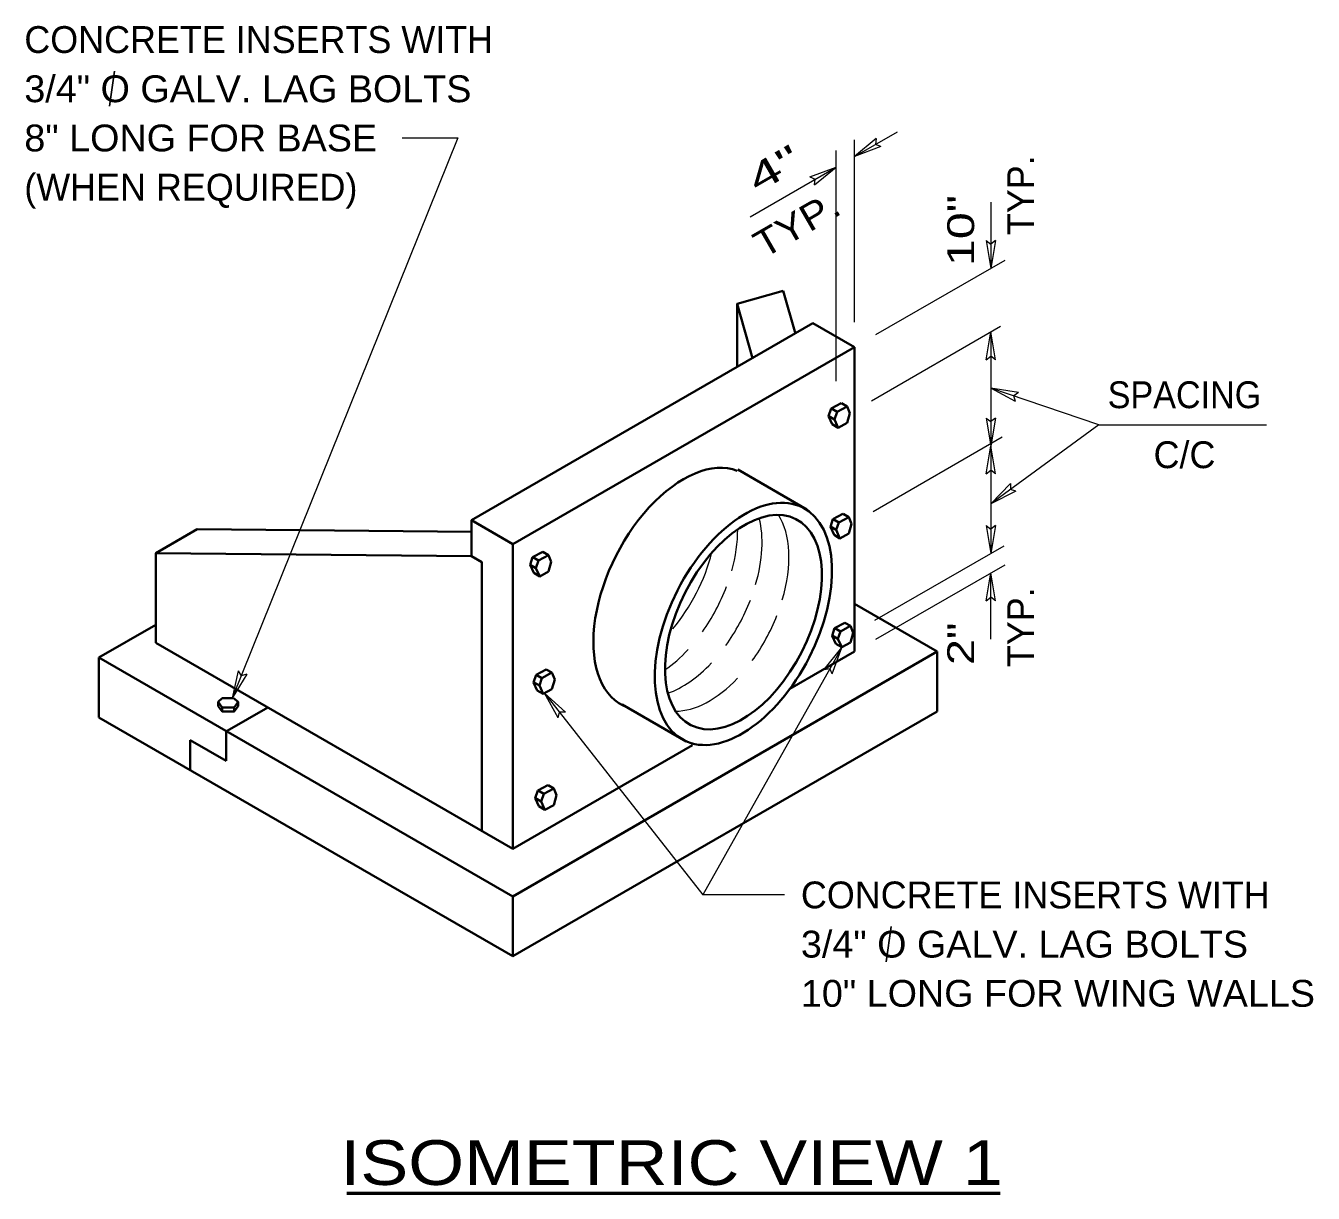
# Model space of a CAD drawing. Extents: x 178962.5 to 178977.5, y 178951.2 to 178972.9.
# Drawn here: x 178962.79 to 178969.26, y 178967.06 to 178972.93 of the extents above; entities that cross this region are included whole.
import ezdxf
from ezdxf.enums import TextEntityAlignment as Align

# ---------------------------------------------------------------- set-up
doc = ezdxf.new("R2010")
doc.units = 0
doc.header["$LTSCALE"] = 0.054
for name, color, linetype, lineweight in [('1', 7, 'Continuous', 35), ('10', 7, 'Continuous', 13), ('12', 7, 'Continuous', 53), ('6', 7, 'Continuous', 13)]:
    doc.layers.add(name, color=color, linetype=linetype, lineweight=lineweight)

msp = doc.modelspace()

# ---------------------------------------------------------------- linework, layer by layer
at = {"layer": '1'}
for p, q in [((178966.65783, 178971.38425), (178966.596, 178971.6)), ((178966.365, 178971.53367), (178966.365, 178971.21692)), ((178965.02958, 178970.44583), (178966.74642, 178971.43708)), ((178966.95458, 178971.31692), (178966.74642, 178971.43708)), ((178965.23767, 178970.32575), (178966.95458, 178971.31692)), ((178966.95458, 178969.78508), (178966.95458, 178971.31692)), ((178966.838, 178971.0075), (178966.82525, 178970.9695)), ((178966.838, 178971.0075), (178966.88842, 178971.0345)), ((178966.83892, 178971.008), (178966.86742, 178970.9915)), ((178966.86742, 178970.9915), (178966.85467, 178970.9535)), ((178966.86742, 178970.9915), (178966.91783, 178971.0185)), ((178966.88925, 178971.035), (178966.91783, 178971.0185)), ((178966.91783, 178971.0185), (178966.93167, 178970.98442)), ((178966.91783, 178970.93525), (178966.93167, 178970.98442)), ((178966.84358, 178970.92883), (178966.82525, 178970.9695)), ((178966.8255, 178970.97025), (178966.85467, 178970.9535)), ((178966.84358, 178970.92883), (178966.87358, 178970.9115)), ((178966.87358, 178970.9115), (178966.85467, 178970.9535)), ((178966.87358, 178970.9115), (178966.91783, 178970.93525)), ((178966.36925, 178970.70042), (178966.71592, 178970.50033)), ((178966.84675, 178970.451), (178966.89717, 178970.478)), ((178966.898, 178970.4785), (178966.92658, 178970.462)), ((178965.03075, 178970.38767), (178963.65083, 178970.40083)), ((178966.84675, 178970.451), (178966.834, 178970.413)), ((178966.85233, 178970.37233), (178966.834, 178970.413)), ((178966.83425, 178970.41375), (178966.86342, 178970.397)), ((178966.84767, 178970.4515), (178966.87617, 178970.435)), ((178966.87617, 178970.435), (178966.86342, 178970.397)), ((178966.87617, 178970.435), (178966.92658, 178970.462)), ((178966.92658, 178970.462), (178966.94042, 178970.42792)), ((178966.92658, 178970.37875), (178966.94042, 178970.42792)), ((178966.85233, 178970.37233), (178966.88233, 178970.355)), ((178966.88233, 178970.355), (178966.86342, 178970.397)), ((178966.88233, 178970.355), (178966.92658, 178970.37875)), ((178963.44275, 178969.83008), (178963.44275, 178970.28058)), ((178965.337, 178970.25975), (178965.38742, 178970.28675)), ((178965.36642, 178970.24375), (178965.41683, 178970.27075)), ((178965.38825, 178970.28725), (178965.41683, 178970.27075)), ((178965.41683, 178970.27075), (178965.43067, 178970.23667)), ((178965.337, 178970.25975), (178965.32425, 178970.22175)), ((178965.34258, 178970.18108), (178965.32425, 178970.22175)), ((178965.3245, 178970.2225), (178965.35367, 178970.20575)), ((178965.33792, 178970.26025), (178965.36642, 178970.24375)), ((178965.36642, 178970.24375), (178965.35367, 178970.20575)), ((178965.37258, 178970.16375), (178965.35367, 178970.20575)), ((178965.41683, 178970.1875), (178965.43067, 178970.23667)), ((178965.34258, 178970.18108), (178965.37258, 178970.16375)), ((178965.37258, 178970.16375), (178965.41683, 178970.1875)), ((178967.37075, 178969.78508), (178966.95458, 178970.02533)), ((178963.15667, 178969.755), (178963.44275, 178969.92017)), ((178966.8555, 178969.90325), (178966.84275, 178969.86525)), ((178966.8555, 178969.90325), (178966.90592, 178969.93025)), ((178966.85642, 178969.90375), (178966.88492, 178969.88725)), ((178966.88492, 178969.88725), (178966.87217, 178969.84925)), ((178966.88492, 178969.88725), (178966.93533, 178969.91425)), ((178966.90675, 178969.93075), (178966.93533, 178969.91425)), ((178966.93533, 178969.91425), (178966.94917, 178969.88017)), ((178963.44275, 178969.83008), (178965.23767, 178968.79375)), ((178966.86108, 178969.82458), (178966.84275, 178969.86525)), ((178966.843, 178969.866), (178966.87217, 178969.84925)), ((178966.86108, 178969.82458), (178966.89108, 178969.80725)), ((178966.89108, 178969.80725), (178966.87217, 178969.84925)), ((178966.89108, 178969.80725), (178966.93533, 178969.831)), ((178966.93533, 178969.831), (178966.94917, 178969.88017)), ((178965.23767, 178968.55342), (178963.15667, 178969.755)), ((178963.15667, 178969.45458), (178963.15667, 178969.755)), ((178966.95458, 178969.78508), (178966.63025, 178969.59767)), ((178967.37075, 178969.48467), (178967.37075, 178969.78508)), ((178965.3545, 178969.6685), (178965.40492, 178969.6955)), ((178965.40575, 178969.696), (178965.43433, 178969.6795)), ((178965.3545, 178969.6685), (178965.34175, 178969.6305)), ((178965.36008, 178969.58983), (178965.34175, 178969.6305)), ((178965.342, 178969.63125), (178965.37117, 178969.6145)), ((178965.35542, 178969.669), (178965.38392, 178969.6525)), ((178965.38392, 178969.6525), (178965.37117, 178969.6145)), ((178965.38392, 178969.6525), (178965.43433, 178969.6795)), ((178965.43433, 178969.6795), (178965.44817, 178969.64542)), ((178965.43433, 178969.59625), (178965.44817, 178969.64542)), ((178965.36008, 178969.58983), (178965.39008, 178969.5725)), ((178965.39008, 178969.5725), (178965.37117, 178969.6145)), ((178965.39008, 178969.5725), (178965.43433, 178969.59625)), ((178963.75633, 178969.53267), (178963.77675, 178969.5505)), ((178963.75633, 178969.53267), (178963.77617, 178969.50467)), ((178963.77617, 178969.50467), (178963.83583, 178969.50467)), ((178963.77617, 178969.50467), (178963.77617, 178969.48325)), ((178963.83317, 178969.5505), (178963.77675, 178969.5505)), ((178963.80083, 178969.38683), (178964.00558, 178969.505)), ((178963.83317, 178969.5505), (178963.85667, 178969.53267)), ((178963.83583, 178969.50467), (178963.85667, 178969.53267)), ((178963.85667, 178969.53267), (178963.85667, 178969.51092)), ((178965.7875, 178969.51883), (178966.1095, 178969.33292)), ((178965.23767, 178968.25317), (178963.15667, 178969.45458)), ((178963.77617, 178969.48325), (178963.83583, 178969.48325)), ((178965.23767, 178968.25317), (178967.37075, 178969.48467)), ((178963.79583, 178969.23575), (178963.79583, 178969.38583)), ((178963.79583, 178969.23575), (178963.61567, 178969.33983)), ((178963.61567, 178969.18958), (178963.61567, 178969.33983)), ((178965.23767, 178968.79375), (178966.14042, 178969.315)), ((178965.36317, 178969.08592), (178965.41358, 178969.11292)), ((178965.41442, 178969.11342), (178965.443, 178969.09692)), ((178965.36317, 178969.08592), (178965.35042, 178969.04792)), ((178965.36875, 178969.00725), (178965.35042, 178969.04792)), ((178965.35067, 178969.04867), (178965.37983, 178969.03192)), ((178965.36408, 178969.08642), (178965.39258, 178969.06992)), ((178965.39258, 178969.06992), (178965.37983, 178969.03192)), ((178965.39258, 178969.06992), (178965.443, 178969.09692)), ((178965.443, 178969.09692), (178965.45683, 178969.06283)), ((178965.443, 178969.01367), (178965.45683, 178969.06283)), ((178965.36875, 178969.00725), (178965.39875, 178968.98992)), ((178965.39875, 178968.98992), (178965.37983, 178969.03192)), ((178965.39875, 178968.98992), (178965.443, 178969.01367))]:
    msp.add_line(p, q, dxfattribs=at)
for points in [[(178966.443, 178971.26183), (178966.365, 178971.53367), (178966.596, 178971.6)], [(178965.02958, 178970.26558), (178963.44275, 178970.28058), (178963.65083, 178970.40083)], [(178965.23767, 178968.79375), (178965.23767, 178970.32575), (178965.02958, 178970.44583), (178965.02958, 178970.26558), (178965.0815, 178970.23558), (178965.0815, 178968.88392)], [(178965.23767, 178968.25317), (178965.23767, 178968.55342), (178967.37075, 178969.78508)], [(178963.75633, 178969.53267), (178963.75633, 178969.51092), (178963.77617, 178969.48325)], [(178963.83583, 178969.50467), (178963.83583, 178969.48325), (178963.85667, 178969.51092)]]:
    msp.add_lwpolyline(points, dxfattribs=at)
msp.add_ellipse((178966.08801, 178970.10054), major_axis=(0.29825, 0.58527), ratio=0.565771, start_param=0.0594664, end_param=3.2155911, dxfattribs=at)
for centre, major_axis in [((178966.39658, 178969.92461), (0.29825, 0.58527)), ((178966.39687, 178969.93368), (0.26407, 0.5182))]:
    msp.add_ellipse(centre, major_axis=major_axis, ratio=0.565771, dxfattribs=at)
at = {"layer": '10', "lineweight": 25}
for p, q in [((178963.21033, 178972.52783), (178963.235, 178972.70433)), ((178967.11425, 178968.22575), (178967.13892, 178968.40225))]:
    msp.add_line(p, q, dxfattribs=at)
at = {"layer": '10'}
for p, q in [((178964.96067, 178972.36858), (178963.82625, 178969.5505)), ((178964.68017, 178972.36858), (178964.96067, 178972.36858)), ((178966.95458, 178972.27525), (178967.17108, 178972.40025)), ((178967.06417, 178972.36542), (178966.95458, 178972.27525)), ((178966.95458, 178971.44192), (178966.95458, 178972.35858)), ((178967.06417, 178972.36542), (178967.06067, 178972.3365)), ((178966.86317, 178971.146), (178966.86317, 178972.30592)), ((178967.0875, 178972.32508), (178966.95458, 178972.27525)), ((178967.0875, 178972.32508), (178967.06067, 178972.3365)), ((178966.43017, 178971.97258), (178966.86317, 178972.22258)), ((178966.73025, 178972.17283), (178966.86317, 178972.22258)), ((178966.75358, 178972.13242), (178966.86317, 178972.22258)), ((178966.73025, 178972.17283), (178966.75708, 178972.16133)), ((178966.75358, 178972.13242), (178966.75708, 178972.16133)), ((178967.64025, 178972.046), (178967.64025, 178971.71267)), ((178967.61692, 178971.85267), (178967.64025, 178971.71267)), ((178967.61692, 178971.85267), (178967.64025, 178971.83517)), ((178967.66358, 178971.85267), (178967.64025, 178971.71267)), ((178967.66358, 178971.85267), (178967.64025, 178971.83517)), ((178967.06283, 178971.37942), (178967.71242, 178971.75433)), ((178967.03992, 178971.04692), (178967.6895, 178971.42183)), ((178967.61692, 178971.25342), (178967.64025, 178971.39342)), ((178967.66358, 178971.25342), (178967.64025, 178971.39342)), ((178967.61692, 178971.25342), (178967.64025, 178971.27092)), ((178967.66358, 178971.25342), (178967.64025, 178971.27092)), ((178967.76533, 178971.0435), (178967.64025, 178971.11058)), ((178967.78033, 178971.08775), (178967.64025, 178971.11058)), ((178968.18383, 178970.92633), (178967.64025, 178971.11058)), ((178967.78033, 178971.08775), (178967.75625, 178971.07125)), ((178967.76533, 178971.0435), (178967.75625, 178971.07125)), ((178967.61692, 178970.95992), (178967.64025, 178970.81992)), ((178967.61692, 178970.95992), (178967.64025, 178970.94242)), ((178967.66358, 178970.95992), (178967.64025, 178970.81992)), ((178967.66358, 178970.95992), (178967.64025, 178970.94242)), ((178968.18383, 178970.92633), (178967.64025, 178970.52908)), ((178968.18383, 178970.92633), (178969.02592, 178970.92633)), ((178967.04867, 178970.49042), (178967.69817, 178970.86542)), ((178967.61692, 178970.67992), (178967.64025, 178970.81992)), ((178967.66358, 178970.67992), (178967.64025, 178970.81992)), ((178967.61692, 178970.67992), (178967.64025, 178970.69742)), ((178967.66358, 178970.67992), (178967.64025, 178970.69742)), ((178967.7395, 178970.6305), (178967.64025, 178970.52908)), ((178967.7395, 178970.6305), (178967.73917, 178970.60133)), ((178967.76708, 178970.59283), (178967.73917, 178970.60133)), ((178967.76708, 178970.59283), (178967.64025, 178970.52908)), ((178967.61692, 178970.419), (178967.64025, 178970.279)), ((178967.61692, 178970.419), (178967.64025, 178970.4015)), ((178967.66358, 178970.419), (178967.64025, 178970.279)), ((178967.66358, 178970.419), (178967.64025, 178970.4015)), ((178967.05742, 178969.94267), (178967.707, 178970.31758)), ((178967.06283, 178969.84758), (178967.71242, 178970.2225)), ((178967.61692, 178970.04083), (178967.64025, 178970.18083)), ((178967.66358, 178970.04083), (178967.64025, 178970.18083)), ((178967.64025, 178969.8475), (178967.64025, 178970.18083)), ((178967.61692, 178970.04083), (178967.64025, 178970.05833)), ((178967.66358, 178970.04083), (178967.64025, 178970.05833)), ((178966.89192, 178969.80675), (178966.19292, 178968.5615)), ((178966.803, 178969.69608), (178966.89192, 178969.80675)), ((178966.84375, 178969.67325), (178966.89192, 178969.80675)), ((178963.85692, 178969.68908), (178963.82625, 178969.5505)), ((178963.85692, 178969.68908), (178963.872, 178969.66417)), ((178966.803, 178969.69608), (178966.83192, 178969.69992)), ((178966.84375, 178969.67325), (178966.83192, 178969.69992)), ((178963.90017, 178969.67167), (178963.82625, 178969.5505)), ((178963.90017, 178969.67167), (178963.872, 178969.66417)), ((178965.46517, 178969.45175), (178965.39717, 178969.57633)), ((178965.50192, 178969.48058), (178965.39717, 178969.57633)), ((178965.39717, 178969.57633), (178966.19292, 178968.5615)), ((178965.46517, 178969.45175), (178965.47275, 178969.47992)), ((178965.50192, 178969.48058), (178965.47275, 178969.47992)), ((178966.6025, 178968.5615), (178966.19292, 178968.5615))]:
    msp.add_line(p, q, dxfattribs=at)
msp.add_lwpolyline([(178967.64025, 178971.39342), (178967.64025, 178970.81992), (178967.64025, 178970.279)], dxfattribs=at)
at = {"layer": '12'}
msp.add_line((178964.40217, 178967.06108), (178967.68817, 178967.06108), dxfattribs=at)
at = {"layer": '6'}
for centre, start_param, end_param in [((178966.23119, 178970.02538), 5.0299348, 5.971403), ((178965.97344, 178970.15992), 5.0526546, 5.4542434), ((178966.09617, 178970.09873), 5.0372371, 5.717281), ((178965.86909, 178970.23327), 4.3271492, 5.085317), ((178965.97344, 178970.15992), 4.4576274, 4.9055802), ((178966.09617, 178970.09873), 4.4428111, 4.8908216), ((178966.23119, 178970.02538), 4.435745, 4.883818), ((178965.97344, 178970.15992), 3.9480854, 4.2514484), ((178966.09617, 178970.09873), 3.6724801, 4.2355185), ((178966.23119, 178970.02538), 3.414113, 4.2278988)]:
    msp.add_ellipse(centre, major_axis=(0.26407, 0.5182), ratio=0.565771, start_param=start_param, end_param=end_param, dxfattribs=at)

# ---------------------------------------------------------------- texts
at = {"layer": '12'}
for s, p in [('CONCRETE INSERTS WITH', (178962.78125, 178972.79608)), ('(WHEN REQUIRED)', (178962.78125, 178972.05358)), ('CONCRETE INSERTS WITH', (178966.68583, 178968.494))]:
    msp.add_text(s, height=0.135, dxfattribs=at).set_placement(p)
at = {"layer": '12', "width": 1.05}
for s, p in [('3/4" O GALV. LAG BOLTS', (178962.78125, 178972.54858)), ('8" LONG FOR BASE', (178962.78125, 178972.30108)), ('3/4" O GALV. LAG BOLTS', (178966.68583, 178968.2465)), ('10" LONG FOR WING WALLS', (178966.68583, 178967.999))]:
    msp.add_text(s, height=0.135, dxfattribs=at).set_placement(p)
at = {"layer": '12'}
for s, rotation, width, p in [('4"', 30.001, 1.65, (178966.58371, 178972.15727)), ('TYP.', 29.998, 1.15, (178966.69846, 178971.87538)), ('10"', 90, 1.35, (178967.55683, 178971.90283)), ('2"', 90, 1.3, (178967.55683, 178969.82475))]:
    msp.add_text(s, height=0.135, rotation=rotation, dxfattribs=dict(at, width=width)).set_placement(p, align=Align.CENTER)
for p in [(178967.8585, 178972.08067), (178967.8585, 178969.908)]:
    msp.add_text('TYP.', height=0.135, rotation=90, dxfattribs=at).set_placement(p, align=Align.CENTER)
for s, height, width, p in [('SPACING', 0.135, 0.95, (178968.61433, 178971.00967)), ('ISOMETRIC VIEW 1', 0.225, 1.2, (178966.03546, 178967.10292))]:
    msp.add_text(s, height=height, dxfattribs=dict(at, width=width)).set_placement(p, align=Align.CENTER)
msp.add_text('C/C', height=0.135, dxfattribs=at).set_placement((178968.61433, 178970.708), align=Align.CENTER)

doc.saveas('drawing.dxf')
